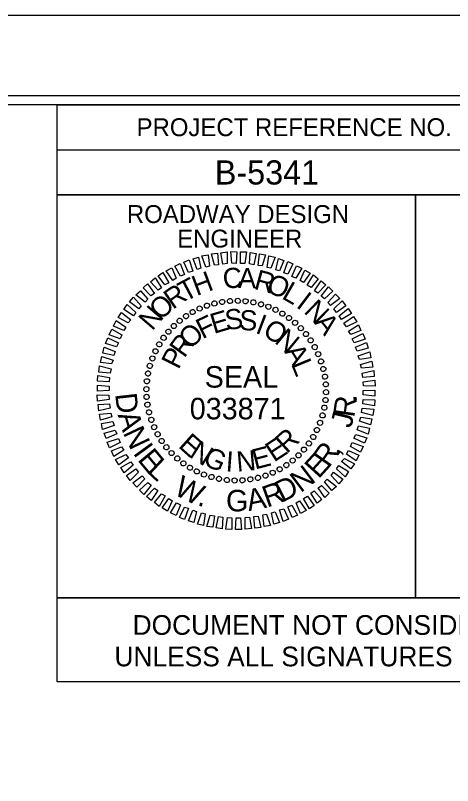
# Model space of a CAD drawing. Extents: x 55823 to 57507, y 47399 to 48499.
# Drawn here: x 57278.5 to 57400.6, y 48284.4 to 48499.4 of the extents above; entities that cross this region are included whole.
import ezdxf

# ---------------------------------------------------------------- set-up
doc = ezdxf.new("R2010")
doc.units = 0
for name, color, linetype in [('Sheet Data Field CELL', 7, 'Continuous'), ('Sheet PE Seal Cell', 7, 'Continuous'), ('Sheet Plot Border Inside CELL', 7, 'Continuous'), ('Sheet Plot Border Outside CELL', 7, 'Continuous'), ('Sheet Sticker Exception Certification CELL', 7, 'Continuous'), ('Sheet Typical CELL', 7, 'Continuous')]:
    doc.layers.add(name, color=color, linetype=linetype)

msp = doc.modelspace()

# ---------------------------------------------------------------- linework, layer by layer
at = {"layer": 'Sheet PE Seal Cell'}
for p, q in [((57340.58, 48419.75), (57340.58, 48419.75)), ((57329.93, 48417.6), (57329.93, 48417.6)), ((57331.93, 48418.4), (57331.93, 48418.4)), ((57334.03, 48419), (57334.03, 48419)), ((57336.23, 48419.4), (57336.23, 48419.4)), ((57338.38, 48419.7), (57338.38, 48419.7)), ((57342.78, 48419.6), (57342.78, 48419.6)), ((57344.93, 48419.25), (57344.93, 48419.25)), ((57347.03, 48418.8), (57347.03, 48418.8)), ((57349.13, 48418.1), (57349.13, 48418.1)), ((57326.08, 48415.45), (57326.08, 48415.45)), ((57327.98, 48416.6), (57327.98, 48416.6)), ((57351.13, 48417.2), (57351.13, 48417.2)), ((57353.08, 48416.2), (57353.08, 48416.2)), ((57324.33, 48414.2), (57324.33, 48414.2)), ((57354.88, 48414.95), (57354.88, 48414.95)), ((57356.63, 48413.6), (57356.63, 48413.6)), ((57321.18, 48411.15), (57321.18, 48411.15)), ((57322.68, 48412.7), (57322.68, 48412.7)), ((57358.18, 48412.1), (57358.18, 48412.1)), ((57319.83, 48409.4), (57319.83, 48409.4)), ((57359.68, 48410.45), (57359.68, 48410.45)), ((57318.58, 48407.6), (57318.58, 48407.6)), ((57360.93, 48408.7), (57360.93, 48408.7)), ((57317.58, 48405.65), (57317.58, 48405.65)), ((57362.08, 48406.8), (57362.08, 48406.8)), ((57363.08, 48404.85), (57363.08, 48404.85)), ((57316.68, 48403.65), (57316.68, 48403.65)), ((57363.88, 48402.85), (57363.88, 48402.85)), ((57315.98, 48401.55), (57315.98, 48401.55)), ((57364.48, 48400.75), (57364.48, 48400.75)), ((57315.53, 48399.45), (57315.53, 48399.45)), ((57364.88, 48398.55), (57364.88, 48398.55)), ((57315.18, 48397.3), (57315.18, 48397.3)), ((57365.18, 48396.4), (57365.18, 48396.4)), ((57315.03, 48395.1), (57315.03, 48395.1)), ((57340.13, 48394.65), (57340.13, 48394.65)), ((57365.23, 48394.2), (57365.23, 48394.2)), ((57315.08, 48392.9), (57315.08, 48392.9)), ((57365.08, 48392), (57365.08, 48392)), ((57315.38, 48390.75), (57315.38, 48390.75)), ((57364.73, 48389.85), (57364.73, 48389.85)), ((57315.78, 48388.55), (57315.78, 48388.55)), ((57364.28, 48387.75), (57364.28, 48387.75)), ((57316.38, 48386.45), (57316.38, 48386.45)), ((57363.58, 48385.65), (57363.58, 48385.65)), ((57317.18, 48384.45), (57317.18, 48384.45)), ((57362.68, 48383.65), (57362.68, 48383.65)), ((57318.18, 48382.5), (57318.18, 48382.5)), ((57361.68, 48381.7), (57361.68, 48381.7)), ((57319.33, 48380.6), (57319.33, 48380.6)), ((57360.43, 48379.9), (57360.43, 48379.9)), ((57320.58, 48378.85), (57320.58, 48378.85)), ((57322.08, 48377.2), (57322.08, 48377.2)), ((57359.08, 48378.15), (57359.08, 48378.15)), ((57323.63, 48375.7), (57323.63, 48375.7)), ((57355.93, 48375.1), (57355.93, 48375.1)), ((57357.58, 48376.6), (57357.58, 48376.6)), ((57325.38, 48374.35), (57325.38, 48374.35)), ((57327.18, 48373.1), (57327.18, 48373.1)), ((57352.28, 48372.7), (57352.28, 48372.7)), ((57354.18, 48373.85), (57354.18, 48373.85)), ((57329.13, 48372.1), (57329.13, 48372.1)), ((57331.13, 48371.2), (57331.13, 48371.2)), ((57333.23, 48370.5), (57333.23, 48370.5)), ((57346.23, 48370.3), (57346.23, 48370.3)), ((57348.33, 48370.9), (57348.33, 48370.9)), ((57350.33, 48371.7), (57350.33, 48371.7)), ((57335.33, 48370.05), (57335.33, 48370.05)), ((57337.48, 48369.7), (57337.48, 48369.7)), ((57339.68, 48369.55), (57339.68, 48369.55)), ((57341.88, 48369.6), (57341.88, 48369.6)), ((57344.03, 48369.9), (57344.03, 48369.9))]:
    msp.add_line(p, q, dxfattribs=at)
for points in [[(57334.03, 48429.65), (57333.23, 48432.85), (57334.88, 48433), (57335.23, 48429.8)], [(57336.43, 48429.95), (57335.88, 48433.15), (57337.58, 48433.35), (57337.63, 48430.1)], [(57338.93, 48430.2), (57338.68, 48433.45), (57340.33, 48433.4), (57340.13, 48430.15)], [(57341.33, 48430.15), (57341.33, 48433.4), (57342.98, 48433.35), (57342.53, 48430.1)], [(57343.83, 48430), (57344.03, 48433.25), (57345.68, 48432.95), (57345.03, 48429.8)], [(57346.23, 48429.6), (57346.68, 48432.8), (57348.33, 48432.55), (57347.43, 48429.45)], [(57326.78, 48427.65), (57325.48, 48430.55), (57326.98, 48431.15), (57328.03, 48427.95)], [(57329.23, 48428.45), (57328.08, 48431.45), (57329.63, 48431.9), (57330.28, 48428.8)], [(57331.63, 48429.1), (57330.58, 48432.25), (57332.28, 48432.6), (57332.68, 48429.35)], [(57348.78, 48429.05), (57349.28, 48432.3), (57350.98, 48431.9), (57349.83, 48428.8)], [(57351.18, 48428.4), (57351.93, 48431.5), (57353.48, 48431), (57352.23, 48428.05)], [(57353.43, 48427.5), (57354.58, 48430.65), (57355.98, 48430.05), (57354.58, 48427.15)], [(57322.43, 48425.4), (57320.58, 48428.1), (57322.13, 48428.9), (57323.38, 48426)], [(57324.58, 48426.6), (57322.98, 48429.4), (57324.53, 48430.1), (57325.68, 48427.05)], [(57355.68, 48426.55), (57356.93, 48429.5), (57358.48, 48428.8), (57356.78, 48426)], [(57320.23, 48424.15), (57318.38, 48426.7), (57319.68, 48427.65), (57321.33, 48424.75)], [(57357.98, 48425.4), (57359.33, 48428.25), (57360.83, 48427.4), (57358.93, 48424.8)], [(57359.93, 48424.05), (57361.68, 48426.95), (57362.98, 48425.9), (57361.03, 48423.45)], [(57316.33, 48421.1), (57314.13, 48423.3), (57315.33, 48424.5), (57317.28, 48421.8)], [(57318.33, 48422.65), (57316.18, 48425.05), (57317.53, 48426.1), (57319.28, 48423.3)], [(57361.98, 48422.55), (57363.83, 48425.3), (57365.13, 48424.2), (57362.93, 48421.85)], [(57314.68, 48419.35), (57312.13, 48421.4), (57313.38, 48422.55), (57315.48, 48420.15)], [(57363.88, 48421), (57365.93, 48423.6), (57367.13, 48422.4), (57364.83, 48420.25)], [(57312.93, 48417.45), (57310.33, 48419.4), (57311.43, 48420.7), (57313.63, 48418.35)], [(57365.68, 48419.25), (57367.83, 48421.6), (57369.03, 48420.4), (57366.43, 48418.45)], [(57311.43, 48415.55), (57308.73, 48417.25), (57309.68, 48418.7), (57312.08, 48416.5)], [(57367.43, 48417.45), (57369.73, 48419.7), (57370.78, 48418.35), (57368.13, 48416.45)], [(57368.93, 48415.5), (57371.38, 48417.6), (57372.33, 48416.15), (57369.53, 48414.55)], [(57309.93, 48413.55), (57307.13, 48415.05), (57308.13, 48416.45), (57310.73, 48414.45)], [(57308.73, 48411.4), (57305.88, 48412.65), (57306.63, 48414.2), (57309.33, 48412.35)], [(57370.23, 48413.45), (57372.88, 48415.35), (57373.83, 48413.85), (57370.93, 48412.45)], [(57307.73, 48409.1), (57304.63, 48410.25), (57305.38, 48411.8), (57308.23, 48410.2)], [(57371.53, 48411.25), (57374.33, 48413), (57374.98, 48411.45), (57372.13, 48410.3)], [(57306.73, 48406.9), (57303.63, 48407.8), (57304.28, 48409.35), (57307.28, 48407.95)], [(57372.53, 48409.1), (57375.48, 48410.6), (57376.13, 48409), (57373.03, 48408)], [(57373.43, 48406.75), (57376.48, 48408.05), (57377.03, 48406.5), (57373.93, 48405.7)], [(57305.98, 48404.5), (57302.88, 48405.15), (57303.23, 48406.8), (57306.38, 48405.55)], [(57374.23, 48404.35), (57377.43, 48405.5), (57377.73, 48403.85), (57374.58, 48403.3)], [(57305.33, 48402.1), (57302.23, 48402.5), (57302.58, 48404.2), (57305.73, 48403.15)], [(57374.83, 48401.95), (57377.98, 48402.9), (57378.28, 48401.2), (57375.13, 48400.9)], [(57304.93, 48399.55), (57301.73, 48399.85), (57301.93, 48401.55), (57305.18, 48400.75)], [(57304.68, 48397.15), (57301.43, 48397.25), (57301.53, 48398.9), (57304.78, 48398.35)], [(57375.28, 48399.55), (57378.53, 48400.25), (57378.68, 48398.55), (57375.48, 48398.35)], [(57304.63, 48394.65), (57301.38, 48394.5), (57301.38, 48396.2), (57304.63, 48395.85)], [(57375.58, 48397.15), (57378.83, 48397.55), (57378.93, 48395.85), (57375.68, 48395.95)], [(57375.63, 48394.65), (57378.88, 48394.8), (57378.88, 48393.1), (57375.63, 48393.45)], [(57304.68, 48392.15), (57301.43, 48391.75), (57301.33, 48393.45), (57304.58, 48393.35)], [(57375.58, 48392.15), (57378.83, 48392.05), (57378.73, 48390.4), (57375.48, 48390.95)], [(57304.98, 48389.75), (57301.73, 48389.05), (57301.58, 48390.75), (57304.78, 48390.95)], [(57375.33, 48389.75), (57378.53, 48389.45), (57378.33, 48387.75), (57375.08, 48388.55)], [(57305.43, 48387.35), (57302.28, 48386.4), (57301.98, 48388.1), (57305.13, 48388.4)], [(57306.03, 48384.95), (57302.83, 48383.8), (57302.53, 48385.45), (57305.68, 48386)], [(57374.93, 48387.2), (57378.03, 48386.8), (57377.68, 48385.1), (57374.53, 48386.15)], [(57306.83, 48382.55), (57303.78, 48381.25), (57303.23, 48382.8), (57306.33, 48383.6)], [(57374.28, 48384.8), (57377.38, 48384.15), (57377.03, 48382.5), (57373.88, 48383.75)], [(57307.73, 48380.2), (57304.78, 48378.7), (57304.13, 48380.3), (57307.23, 48381.3)], [(57373.53, 48382.4), (57376.63, 48381.5), (57375.98, 48379.95), (57372.98, 48381.35)], [(57308.73, 48378.05), (57305.93, 48376.3), (57305.28, 48377.85), (57308.13, 48379)], [(57372.53, 48380.2), (57375.63, 48379.05), (57374.88, 48377.5), (57372.03, 48379.1)], [(57310.03, 48375.85), (57307.38, 48373.95), (57306.43, 48375.45), (57309.33, 48376.85)], [(57371.53, 48377.9), (57374.38, 48376.65), (57373.63, 48375.1), (57370.93, 48376.95)], [(57311.33, 48373.8), (57308.88, 48371.7), (57307.93, 48373.15), (57310.73, 48374.75)], [(57370.33, 48375.75), (57373.13, 48374.25), (57372.13, 48372.85), (57369.53, 48374.85)], [(57312.83, 48371.85), (57310.53, 48369.6), (57309.48, 48370.95), (57312.13, 48372.85)], [(57368.83, 48373.75), (57371.53, 48372.05), (57370.58, 48370.6), (57368.18, 48372.8)], [(57314.58, 48370.05), (57312.43, 48367.7), (57311.23, 48368.9), (57313.83, 48370.85)], [(57367.33, 48371.85), (57369.93, 48369.9), (57368.83, 48368.6), (57366.63, 48370.95)], [(57316.38, 48368.3), (57314.33, 48365.7), (57313.13, 48366.9), (57315.43, 48369.05)], [(57363.93, 48368.2), (57366.13, 48366), (57364.93, 48364.8), (57362.98, 48367.5)], [(57365.58, 48369.95), (57368.13, 48367.9), (57366.88, 48366.75), (57364.78, 48369.15)], [(57318.28, 48366.75), (57316.43, 48364), (57315.13, 48365.1), (57317.33, 48367.45)], [(57361.93, 48366.65), (57364.08, 48364.25), (57362.73, 48363.2), (57360.98, 48366)], [(57320.33, 48365.25), (57318.58, 48362.35), (57317.28, 48363.4), (57319.23, 48365.85)], [(57322.28, 48363.9), (57320.93, 48361.05), (57319.43, 48361.9), (57321.33, 48364.5)], [(57357.83, 48363.9), (57359.68, 48361.2), (57358.13, 48360.4), (57356.88, 48363.3)], [(57360.03, 48365.15), (57361.88, 48362.6), (57360.58, 48361.65), (57358.93, 48364.55)], [(57324.58, 48362.75), (57323.33, 48359.8), (57321.78, 48360.5), (57323.48, 48363.3)], [(57326.83, 48361.8), (57325.68, 48358.65), (57324.28, 48359.25), (57325.68, 48362.15)], [(57355.68, 48362.7), (57357.28, 48359.9), (57355.73, 48359.2), (57354.58, 48362.25)], [(57329.08, 48360.9), (57328.33, 48357.8), (57326.78, 48358.3), (57328.03, 48361.25)], [(57331.48, 48360.25), (57330.98, 48357), (57329.28, 48357.4), (57330.43, 48360.5)], [(57334.03, 48359.7), (57333.58, 48356.5), (57331.93, 48356.75), (57332.83, 48359.85)], [(57346.23, 48359.65), (57347.03, 48356.45), (57345.38, 48356.3), (57345.03, 48359.5)], [(57348.63, 48360.2), (57349.68, 48357.05), (57347.98, 48356.7), (57347.58, 48359.95)], [(57351.03, 48360.85), (57352.18, 48357.85), (57350.63, 48357.4), (57349.98, 48360.5)], [(57353.48, 48361.65), (57354.78, 48358.75), (57353.28, 48358.15), (57352.23, 48361.35)], [(57336.43, 48359.3), (57336.23, 48356.05), (57334.58, 48356.35), (57335.23, 48359.5)], [(57338.93, 48359.15), (57338.93, 48355.9), (57337.28, 48355.95), (57337.73, 48359.2)], [(57341.33, 48359.1), (57341.58, 48355.85), (57339.93, 48355.9), (57340.13, 48359.15)], [(57343.83, 48359.35), (57344.38, 48356.15), (57342.68, 48355.95), (57342.63, 48359.2)]]:
    msp.add_lwpolyline(points, close=True, dxfattribs=at)
for centre, major_axis in [((57334.06, 48418.98), (-0.174, 0.699)), ((57336.21, 48419.42), (-0.113, 0.711)), ((57338.38, 48419.66), (-0.05, 0.718)), ((57340.57, 48419.72), (0.013, 0.72)), ((57342.75, 48419.59), (0.075, 0.716)), ((57344.92, 48419.26), (0.137, 0.707)), ((57329.93, 48417.56), (-0.293, 0.658)), ((57331.96, 48418.36), (-0.234, 0.681)), ((57347.04, 48418.75), (0.198, 0.692)), ((57349.12, 48418.06), (0.258, 0.672)), ((57351.12, 48417.19), (0.316, 0.647)), ((57326.11, 48415.44), (-0.403, 0.597)), ((57327.97, 48416.58), (-0.349, 0.63)), ((57353.05, 48416.14), (0.371, 0.617)), ((57354.87, 48414.94), (0.423, 0.582)), ((57322.71, 48412.69), (-0.5, 0.518)), ((57324.35, 48414.14), (-0.453, 0.56)), ((57356.58, 48413.57), (0.472, 0.543)), ((57321.2, 48411.1), (-0.543, 0.472)), ((57358.17, 48412.07), (0.518, 0.5)), ((57359.62, 48410.43), (0.56, 0.453)), ((57319.84, 48409.39), (-0.582, 0.423)), ((57360.92, 48408.67), (0.597, 0.403)), ((57318.63, 48407.56), (-0.617, 0.371)), ((57362.07, 48406.8), (0.63, 0.349)), ((57317.59, 48405.64), (-0.647, 0.316)), ((57363.04, 48404.85), (0.658, 0.293)), ((57316.72, 48403.63), (-0.672, 0.258)), ((57363.84, 48402.81), (0.681, 0.234)), ((57316.02, 48401.56), (-0.692, 0.198)), ((57364.46, 48400.71), (0.699, 0.174)), ((57315.51, 48399.43), (-0.707, 0.137)), ((57364.9, 48398.57), (0.711, 0.113)), ((57315.19, 48397.27), (-0.716, 0.075)), ((57365.15, 48396.4), (0.718, 0.05)), ((57315.05, 48395.08), (-0.72, 0.013)), ((57365.21, 48394.21), (0.72, -0.013)), ((57315.11, 48392.9), (-0.718, -0.05)), ((57365.07, 48392.02), (0.716, -0.075)), ((57315.36, 48390.72), (-0.711, -0.113)), ((57364.75, 48389.86), (0.707, -0.137)), ((57315.79, 48388.58), (-0.699, -0.174)), ((57364.24, 48387.73), (0.692, -0.198)), ((57316.42, 48386.48), (-0.681, -0.234)), ((57363.54, 48385.66), (0.672, -0.258)), ((57317.22, 48384.44), (-0.658, -0.293)), ((57318.19, 48382.49), (-0.63, -0.349)), ((57362.67, 48383.65), (0.647, -0.316)), ((57319.34, 48380.62), (-0.597, -0.403)), ((57361.63, 48381.73), (0.617, -0.371)), ((57320.64, 48378.86), (-0.56, -0.453)), ((57359.06, 48378.19), (0.543, -0.472)), ((57360.42, 48379.9), (0.582, -0.423)), ((57322.09, 48377.22), (-0.518, -0.5)), ((57357.55, 48376.6), (0.5, -0.518)), ((57323.68, 48375.72), (-0.472, -0.543)), ((57325.39, 48374.36), (-0.423, -0.582)), ((57354.15, 48373.85), (0.403, -0.597)), ((57355.91, 48375.15), (0.453, -0.56)), ((57327.21, 48373.15), (-0.371, -0.617)), ((57329.14, 48372.1), (-0.316, -0.647)), ((57350.33, 48371.73), (0.293, -0.658)), ((57352.29, 48372.71), (0.349, -0.63)), ((57331.14, 48371.23), (-0.258, -0.672)), ((57333.22, 48370.54), (-0.198, -0.692)), ((57335.34, 48370.03), (-0.137, -0.707)), ((57337.51, 48369.7), (-0.075, -0.716)), ((57339.69, 48369.57), (-0.013, -0.72)), ((57341.88, 48369.63), (0.05, -0.718)), ((57344.05, 48369.87), (0.113, -0.711)), ((57346.2, 48370.31), (0.174, -0.699)), ((57348.3, 48370.93), (0.234, -0.681))]:
    msp.add_ellipse(centre, major_axis=major_axis, ratio=0.999708, dxfattribs=at)
at = {"layer": 'Sheet Plot Border Inside CELL'}
msp.add_lwpolyline([(57502.66, 48476.93), (55836.16, 48476.93), (55836.16, 47421.83), (57502.66, 47421.83)], close=True, dxfattribs=at)
at = {"layer": 'Sheet Plot Border Outside CELL'}
msp.add_lwpolyline([(57507.16, 48499.38), (55823.16, 48499.38), (55823.16, 47399.38), (57507.16, 47399.38)], close=True, dxfattribs=at)
at = {"layer": 'Sheet Sticker Exception Certification CELL'}
for p, q in [((57290.13, 48313.33), (57290.13, 48336.83)), ((57290.13, 48336.83), (57490.16, 48336.83)), ((57490.16, 48313.33), (57290.13, 48313.33))]:
    msp.add_line(p, q, dxfattribs=at)
at = {"layer": 'Sheet Typical CELL'}
for p, q in [((57290.11, 48461.83), (57490.16, 48461.83)), ((57390.16, 48449.33), (57390.16, 48336.88))]:
    msp.add_line(p, q, dxfattribs=at)
for points in [[(57490.16, 48474.38), (55990.16, 48474.38), (55990.16, 47424.38), (57490.16, 47424.38)], [(57290.11, 48474.38), (57490.16, 48474.38), (57490.16, 48449.33), (57290.11, 48449.33)], [(57290.11, 48449.33), (57390.16, 48449.33), (57390.16, 48336.83), (57290.11, 48336.83)], [(57390.16, 48449.33), (57490.16, 48449.33), (57490.16, 48336.83), (57390.16, 48336.83)]]:
    msp.add_lwpolyline(points, close=True, dxfattribs=at)

# ---------------------------------------------------------------- texts
at = {"layer": 'Sheet Data Field CELL'}
msp.add_text('B-5341', height=6.75, dxfattribs=at).set_placement((57334.17, 48452.18))
at = {"layer": 'Sheet PE Seal Cell'}
for s, height, rotation, p in [('C', 5.64, 6.2199, (57336.68, 48423)), ('A', 5.64, 359.0203, (57340.63, 48423.3)), ('R', 5.64, 344.6211, (57344.83, 48423.1)), ('T', 5.64, 27.8198, (57325.83, 48419.35)), ('H', 5.64, 20.6195, (57329.08, 48421)), ('O', 5.64, 337.4212, (57348.18, 48422.35)), ('L', 5.64, 330.2209, (57352.58, 48420.5)), ('R', 5.64, 35.0205, (57322.43, 48417.15)), ('I', 5.64, 323.0201, (57356.63, 48418.1)), ('O', 5.64, 42.2217, (57318.98, 48414.05)), ('N', 5.64, 315.8189, (57358.78, 48416.55)), ('N', 5.64, 49.4235, (57316.68, 48411.15)), ('S', 5.64, 7.2556, (57337.33, 48411.5)), ('F', 5.64, 25.967, (57330.68, 48408.95)), ('E', 5.64, 16.6111, (57333.88, 48410.45)), ('S', 5.64, 357.9004, (57340.93, 48411.55)), ('I', 5.64, 339.1896, (57345.23, 48410.85)), ('A', 5.64, 308.6172, (57361.73, 48413.6)), ('O', 5.64, 329.8335, (57347.23, 48410.15)), ('O', 5.64, 44.6812, (57327.38, 48406)), ('N', 5.64, 320.4766, (57350.58, 48408.15)), ('R', 5.64, 54.0397, (57325.63, 48403.55)), ('P', 5.64, 63.3989, (57324.03, 48400.35)), ('A', 5.64, 301.7603, (57353.43, 48405.55)), ('L', 5.64, 292.4008, (57355.38, 48402.1)), ('SEAL', 5.998, 360, (57331.33, 48395.49)), ('D', 6, 276.5178, (57306.32, 48393.71)), ('R', 6, 81.8439, (57373.08, 48386.99)), ('.', 6, 89.3242, (57373.79, 48391.34)), ('A', 6, 286.3936, (57306.98, 48387.92)), ('J', 6, 76.5861, (57372.24, 48384)), ('N', 6, 295.2339, (57308.41, 48382.91)), ('R', 5.64, 42.4814, (57354.23, 48376.9)), ('E', 5.64, 318.2769, (57323.73, 48379)), ('E', 5.64, 33.1241, (57350.68, 48374.55)), ('I', 6, 305.9598, (57311.15, 48377.21)), ('N', 5.64, 327.634, (57326.73, 48376.3)), ('E', 5.64, 14.4118, (57345.38, 48372.6)), ('R', 6, 54.8717, (57366.02, 48372.88)), ('E', 6, 309.7617, (57312.37, 48375.32)), ('G', 5.64, 336.9902, (57330.53, 48374.05)), ('I', 5.64, 355.7012, (57337.08, 48372.15)), ('N', 5.64, 5.0564, (57340.43, 48372)), ('E', 6, 47.7624, (57363.13, 48369.84)), (',', 6, 62.352, (57368.63, 48376.43)), ('L', 6, 316.871, (57314.97, 48372.04)), ('N', 6, 37.0366, (57358.11, 48365.99)), ('W', 6, 333.3462, (57322.42, 48365.83)), ('D', 6, 27.1608, (57352.93, 48363.34)), ('R', 6, 19.6805, (57348.74, 48361.94)), ('G', 6, 0.1144, (57337.29, 48360.94)), ('A', 6, 10.8402, (57343.62, 48361)), ('.', 6, 345.8802, (57329.09, 48362.67))]:
    msp.add_text(s, height=height, rotation=rotation, dxfattribs=at).set_placement(p)
msp.add_text('033871', height=5.998, dxfattribs=at).set_placement((57327.16, 48386.64))
at = {"layer": 'Sheet Sticker Exception Certification CELL'}
for s, p in [('DOCUMENT NOT CONSIDERED FINAL', (57311.2, 48326.49)), ('UNLESS ALL SIGNATURES COMPLETED', (57306.13, 48317.69))]:
    msp.add_text(s, height=5.5, dxfattribs=at).set_placement(p)
at = {"layer": 'Sheet Typical CELL'}
for s, height, p in [('PROJECT REFERENCE NO.', 5.0001, (57312.31, 48465.68)), ('ROADWAY DESIGN', 5.0001, (57309.61, 48441.43)), ('ENGINEER', 5, (57323.66, 48434.58))]:
    msp.add_text(s, height=height, dxfattribs=at).set_placement(p)

doc.saveas('drawing.dxf')
